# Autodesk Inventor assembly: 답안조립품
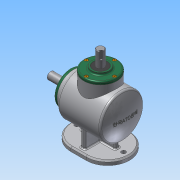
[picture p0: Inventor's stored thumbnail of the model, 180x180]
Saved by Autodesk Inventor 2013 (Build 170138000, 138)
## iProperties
Created: 2016-04
Part Number: 답안조립품
Document SubType Name: Assembly
Designer: Administrator
Author: Administrator
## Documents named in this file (14)
- C:\Users\Administrator\Desktop\460407V1006\답안조립품.iam
- C:\Users\Administrator\Desktop\460407V1006\M4.ipt
- C:\Users\Administrator\Desktop\460407V1006\메인 베벨기어.ipt
- C:\Users\Administrator\Desktop\460407V1006\메인 축.ipt
- 메인 축.ipt
- C:\Users\Administrator\Desktop\460407V1006\베어링 6203.ipt
- C:\Users\Administrator\Desktop\460407V1006\본체.ipt
- C:\Users\Administrator\Desktop\460407V1006\서브 베벨기어.ipt
- C:\Users\Administrator\Desktop\460407V1006\서브 축.ipt
- 서브 축.ipt
- C:\Users\Administrator\Desktop\460407V1006\오일실 17 32 8.ipt
- C:\Users\Administrator\Desktop\460407V1006\커버.ipt
- C:\Users\Administrator\Desktop\460407V1006\키 5x5.ipt
- C:\Users\Administrator\Desktop\460407V1006\키 4x4.ipt
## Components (8 placed, 1 different names)
1. M4:1
2. M4:3
3. M4:4
4. M4:5
5. M4:2
6. M4:6
7. M4:7
8. M4:8
